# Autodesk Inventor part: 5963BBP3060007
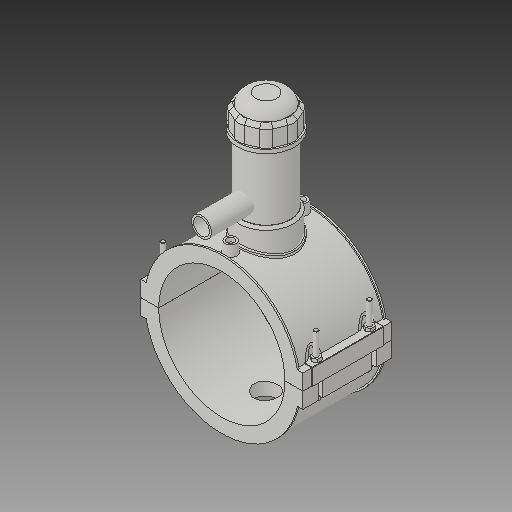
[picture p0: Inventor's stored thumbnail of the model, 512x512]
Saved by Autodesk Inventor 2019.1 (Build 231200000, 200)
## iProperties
Created: 2017-07
Part Number: 5963BBP3060007
Material: Generic
Description: PLASSON TAPPING SADDLE 6''IPS x 3/4''IPS
Document SubType Name: Modeling
Designer: KIM
Density: 1 g/cm^3
Appearance: Default
Author: KIM
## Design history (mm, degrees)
derived "5963BBP_5963BUP.ipt"
feature "Solid1::5963BBP_5963BUP.ipt"
feature "Solid2::5963BBP_5963BUP.ipt"
feature "Solid3::5963BBP_5963BUP.ipt"
tag "TaggingFeature1"
body "Solid1"
body "Solid2"
body "Solid3"
other parameters: "d0" = 168, "d2" = 215.9, "d3" = 42, "d4" = 118.11, "d5" = 0, "d6" = 0.1, "d8" = 0, "d19" = 6, "d20" = 6, "d21" = 70.866, "d23" = 0, "d24" = 35.433, "d26" = 0, "d27" = 3, "d28" = 3, "d29" = 3, "d30" = 56, "d31" = 6, "d32" = 0, "d33" = 0, "d34" = 0.6, "d40" = 104.832, "d41" = 75.6, "d43" = 0, "d45" = 0, "d47" = 171.666, "d70" = 15, "d72" = 0, "d73" = 6, "d75" = 5, "d76" = 0, "d77" = 8.4, "d78" = 114, "d79" = 15, "d80" = 47.244, "d82" = 5 deg, "d84" = 4, "d85" = 14, "d86" = 0, "d87" = 3, "d88" = 0, "d89" = 1, "d90" = 1, "d91" = 94.488, "d92" = 0, "d93" = 0.5, "d94" = 88.42105, "d96" = 205.632, "d97" = 2.3622, "d98" = 0, "d102" = 1.68, "d120" = 140 deg, "d121" = 24.228, "d122" = 20 deg, "d123" = 403.2, "d124" = 120.96, "d126" = 0, "d143" = 173.04, "d145" = 25.84615, "d149" = 2.52, "d150" = 28.43077, "d153" = 118.11, "d154" = 0, "d156" = 100.8, "d157" = 160 deg, "d159" = 6.72, "d161" = 2.52, "d162" = 70.866, "d163" = 0, "d164" = 84, "d167" = 16.8, "d168" = 98.34146, "d170" = 3.2805, "d172" = 0, "d173" = 1, "d175" = 84, "d176" = 20 deg, "d177" = 11.76, "d178" = 33.6, "d180" = 0, "d183" = 13.44, "d184" = 9.408, "d185" = 38.38575, "d186" = 38.38575, "d187" = 100.8, "d188" = 10.08, "d189" = 11.76, "d190" = 0, "d191" = 151.2, "d193" = 6.9984, "d194" = 4.13385, "d195" = 90 deg, "d197" = 0, "d199" = 0, "d200" = 16.8, "d202" = 0, "d203" = 177.038, "d204" = 71.82, "d205" = 52.92, "d206" = 64.26, "d207" = 132.7785, "d208" = 138.08964, "d209" = 164.64534, "d210" = 65.016, "d211" = 75.6, "d212" = 60.48, "d213" = 46.5516, "d216" = 0, "d217" = 16.8, "d218" = 16.8, "d219" = 3.36, "d222" = 168, "d224" = 0, "d225" = 65.024, "d226" = 26.6, "d227" = 21.28, "d228" = 86.106, "d230" = 5.04, "d_" = 168, "B_" = 215.9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
